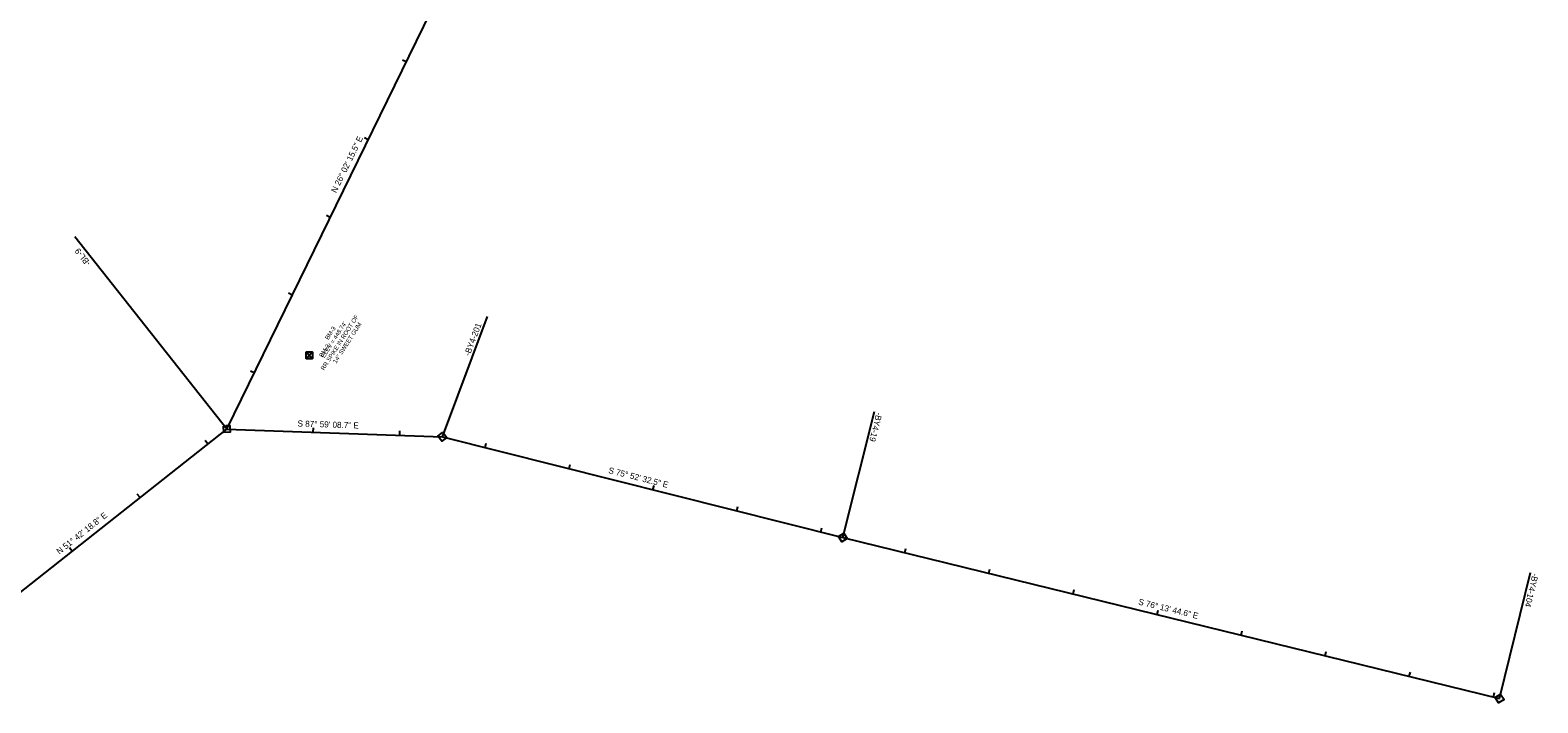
# Model space of a CAD drawing. Extents: x 1975258 to 1978652, y 778250 to 783549.
# Drawn here: x 1976910 to 1978652, y 779936 to 780713 of the extents above; entities that cross this region are included whole.
import ezdxf

# ---------------------------------------------------------------- set-up
doc = ezdxf.new("R2010")
doc.units = 0
for name, color, linetype in [('Prop Drainage Structure Drop Inlet Grate 2 Narrow Slots and Flat Grates 840 29 Label', 7, 'Continuous'), ('Prop Drainage Structure Drop Inlet Grate 2 Narrow Slots and Sag Grates 840 24 CELL', 7, 'Continuous'), ('Prop Erosion Rip Rap Pad at Outlet CELL', 7, 'Continuous'), ('Prop SS Fill Line', 7, 'Continuous'), ('Prop SS Transition Line', 7, 'Continuous'), ('Sheet Data Field CELL', 7, 'Continuous'), ('Sheet Sticker Preliminary CELL', 7, 'Continuous'), ('Sheet Typical CELL', 7, 'Continuous')]:
    doc.layers.add(name, color=color, linetype=linetype)

msp = doc.modelspace()

# ---------------------------------------------------------------- linework, layer by layer
at = {"layer": 'Prop Drainage Structure Drop Inlet Grate 2 Narrow Slots and Sag Grates 840 24 CELL'}
for p, q in [((1977137.5, 780252), (1976961.9, 780474.3)), ((1977386.6, 780243.3), (1977438.9, 780382.3)), ((1977849.3, 780126.9), (1977885.9, 780272.3)), ((1978607.9, 779940.9), (1978643.6, 780086.6))]:
    msp.add_line(p, q, dxfattribs=at)
at = {"layer": 'Prop SS Transition Line'}
for p, q in [((1977137.6, 780252.1), (1977137.6, 780252.1)), ((1977386.6, 780243.3), (1977386.6, 780243.3)), ((1977849.3, 780126.9), (1977849.3, 780126.9)), ((1978607.9, 779940.9), (1978607.9, 779940.9))]:
    msp.add_line(p, q, dxfattribs=at)
for points in [[(1977133.6, 780255.4), (1977140.9, 780256.1), (1977141.6, 780248.7), (1977134.3, 780248)], [(1977387.3, 780248.5), (1977391.8, 780242.6), (1977385.9, 780238.1), (1977381.4, 780244)], [(1977850.5, 780131.9), (1977854.4, 780125.6), (1977848.1, 780121.7), (1977844.2, 780128)], [(1978609.1, 779946), (1978613, 779939.7), (1978606.7, 779935.8), (1978602.8, 779942.1)]]:
    msp.add_lwpolyline(points, close=True, dxfattribs=at)
at = {"layer": 'Sheet Data Field CELL'}
for p, q in [((1977344.9, 780676.4), (1977340.4, 780678.5)), ((1977301, 780586.5), (1977296.5, 780588.7)), ((1977257.1, 780496.7), (1977252.6, 780498.8)), ((1977213.2, 780406.8), (1977208.7, 780409)), ((1977169.3, 780317), (1977164.8, 780319.1)), ((1977137.6, 780252.1), (1977137.7, 780257.1)), ((1977237.5, 780248.5), (1977237.7, 780253.5)), ((1977337.4, 780245), (1977337.6, 780250)), ((1977115.8, 780234.8), (1977112.7, 780238.8)), ((1977435.9, 780230.9), (1977437.1, 780235.7)), ((1977532.9, 780206.5), (1977534.1, 780211.3)), ((1977037.3, 780172.9), (1977034.2, 780176.8)), ((1977629.8, 780182.1), (1977631.1, 780186.9)), ((1977726.8, 780157.7), (1977728, 780162.5)), ((1977823.8, 780133.3), (1977825, 780138.1)), ((1976958.8, 780110.9), (1976955.7, 780114.8)), ((1977920.9, 780109.3), (1977922.1, 780114.2)), ((1978018, 780085.5), (1978019.2, 780090.4)), ((1978115.1, 780061.7), (1978116.3, 780066.6)), ((1978212.2, 780037.9), (1978213.4, 780042.8)), ((1978309.4, 780014.1), (1978310.6, 780019)), ((1978406.5, 779990.3), (1978407.7, 779995.2)), ((1978503.6, 779966.5), (1978504.8, 779971.4)), ((1978600.7, 779942.7), (1978601.9, 779947.6))]:
    msp.add_line(p, q, dxfattribs=at)
at = {"layer": 'Sheet Sticker Preliminary CELL'}
msp.add_line((1977232.9, 780337.3), (1977232.9, 780337.3), dxfattribs=at)
msp.add_lwpolyline([(1977229.3, 780340.9), (1977236.5, 780340.9), (1977236.5, 780333.7), (1977229.3, 780333.7)], close=True, dxfattribs=at)
for points in [[(1977236.5, 780340.9), (1977229.3, 780333.7), (1977232.9, 780337.3), (1977236.5, 780333.7), (1977229.3, 780340.9)], [(1977232.9, 780337.3), (1977236.5, 780340.9), (1977229.3, 780340.9), (1977232.9, 780337.3)], [(1977232.9, 780337.3), (1977229.3, 780333.7), (1977236.5, 780333.7), (1977232.9, 780337.3)]]:
    msp.add_lwpolyline(points, dxfattribs=at)
at = {"layer": 'Sheet Typical CELL'}
for p, q in [((1977137.6, 780252.1), (1977437.3, 780865.6)), ((1976819.3, 780000.7), (1977137.6, 780252.1)), ((1977137.6, 780252.1), (1977386.6, 780243.3)), ((1977386.6, 780243.3), (1977849.3, 780126.9)), ((1977849.3, 780126.9), (1978607.9, 779940.9))]:
    msp.add_line(p, q, dxfattribs=at)

# ---------------------------------------------------------------- texts
at = {"layer": 'Prop Drainage Structure Drop Inlet Grate 2 Narrow Slots and Flat Grates 840 29 Label'}
for s, rotation, p in [('N 26%%d 02\' 15.5" E', 63.9624, (1977263.9, 780524.4)), ('S 87%%d 59\' 08.7" E', 357.9858, (1977219.2, 780255.2)), ('S 75%%d 52\' 32.5" E', 345.8757, (1977577.9, 780201.4)), ('N 51%%d 42\' 18.8" E', 38.2948, (1976944.2, 780107)), ('S 76%%d 13\' 44.6" E', 346.229, (1978190.1, 780049.5))]:
    msp.add_text(s, height=7, rotation=rotation, dxfattribs=at).set_placement(p)
at = {"layer": 'Prop Drainage Structure Drop Inlet Grate 2 Narrow Slots and Sag Grates 840 24 CELL'}
for s, rotation, p in [('-BL-9', 128.2994, (1976980.9, 780444)), ('-BY4-201', 69.3615, (1977418.1, 780336.1)), ('-BY4-19', 255.8757, (1977888.1, 780271.9)), ('-BY4-104', 256.229, (1978646.2, 780085.9))]:
    msp.add_text(s, height=7, rotation=rotation, dxfattribs=at).set_placement(p)
at = {"layer": 'Prop Erosion Rip Rap Pad at Outlet CELL'}
msp.add_text('BM-3', height=5, rotation=57.255, dxfattribs=at).set_placement((1977248, 780334.5))
at = {"layer": 'Prop SS Fill Line'}
for s, p in [('RR SPIKE IN ROOT OF', (1977249.9, 780319.5)), ("ELEV = 448.74'", (1977250.3, 780333.9)), ('BM-3', (1977254.8, 780354.8)), ('14" SWEET GUM', (1977264, 780327.5))]:
    msp.add_text(s, height=5, rotation=57.255, dxfattribs=at).set_placement(p)

doc.saveas('drawing.dxf')
